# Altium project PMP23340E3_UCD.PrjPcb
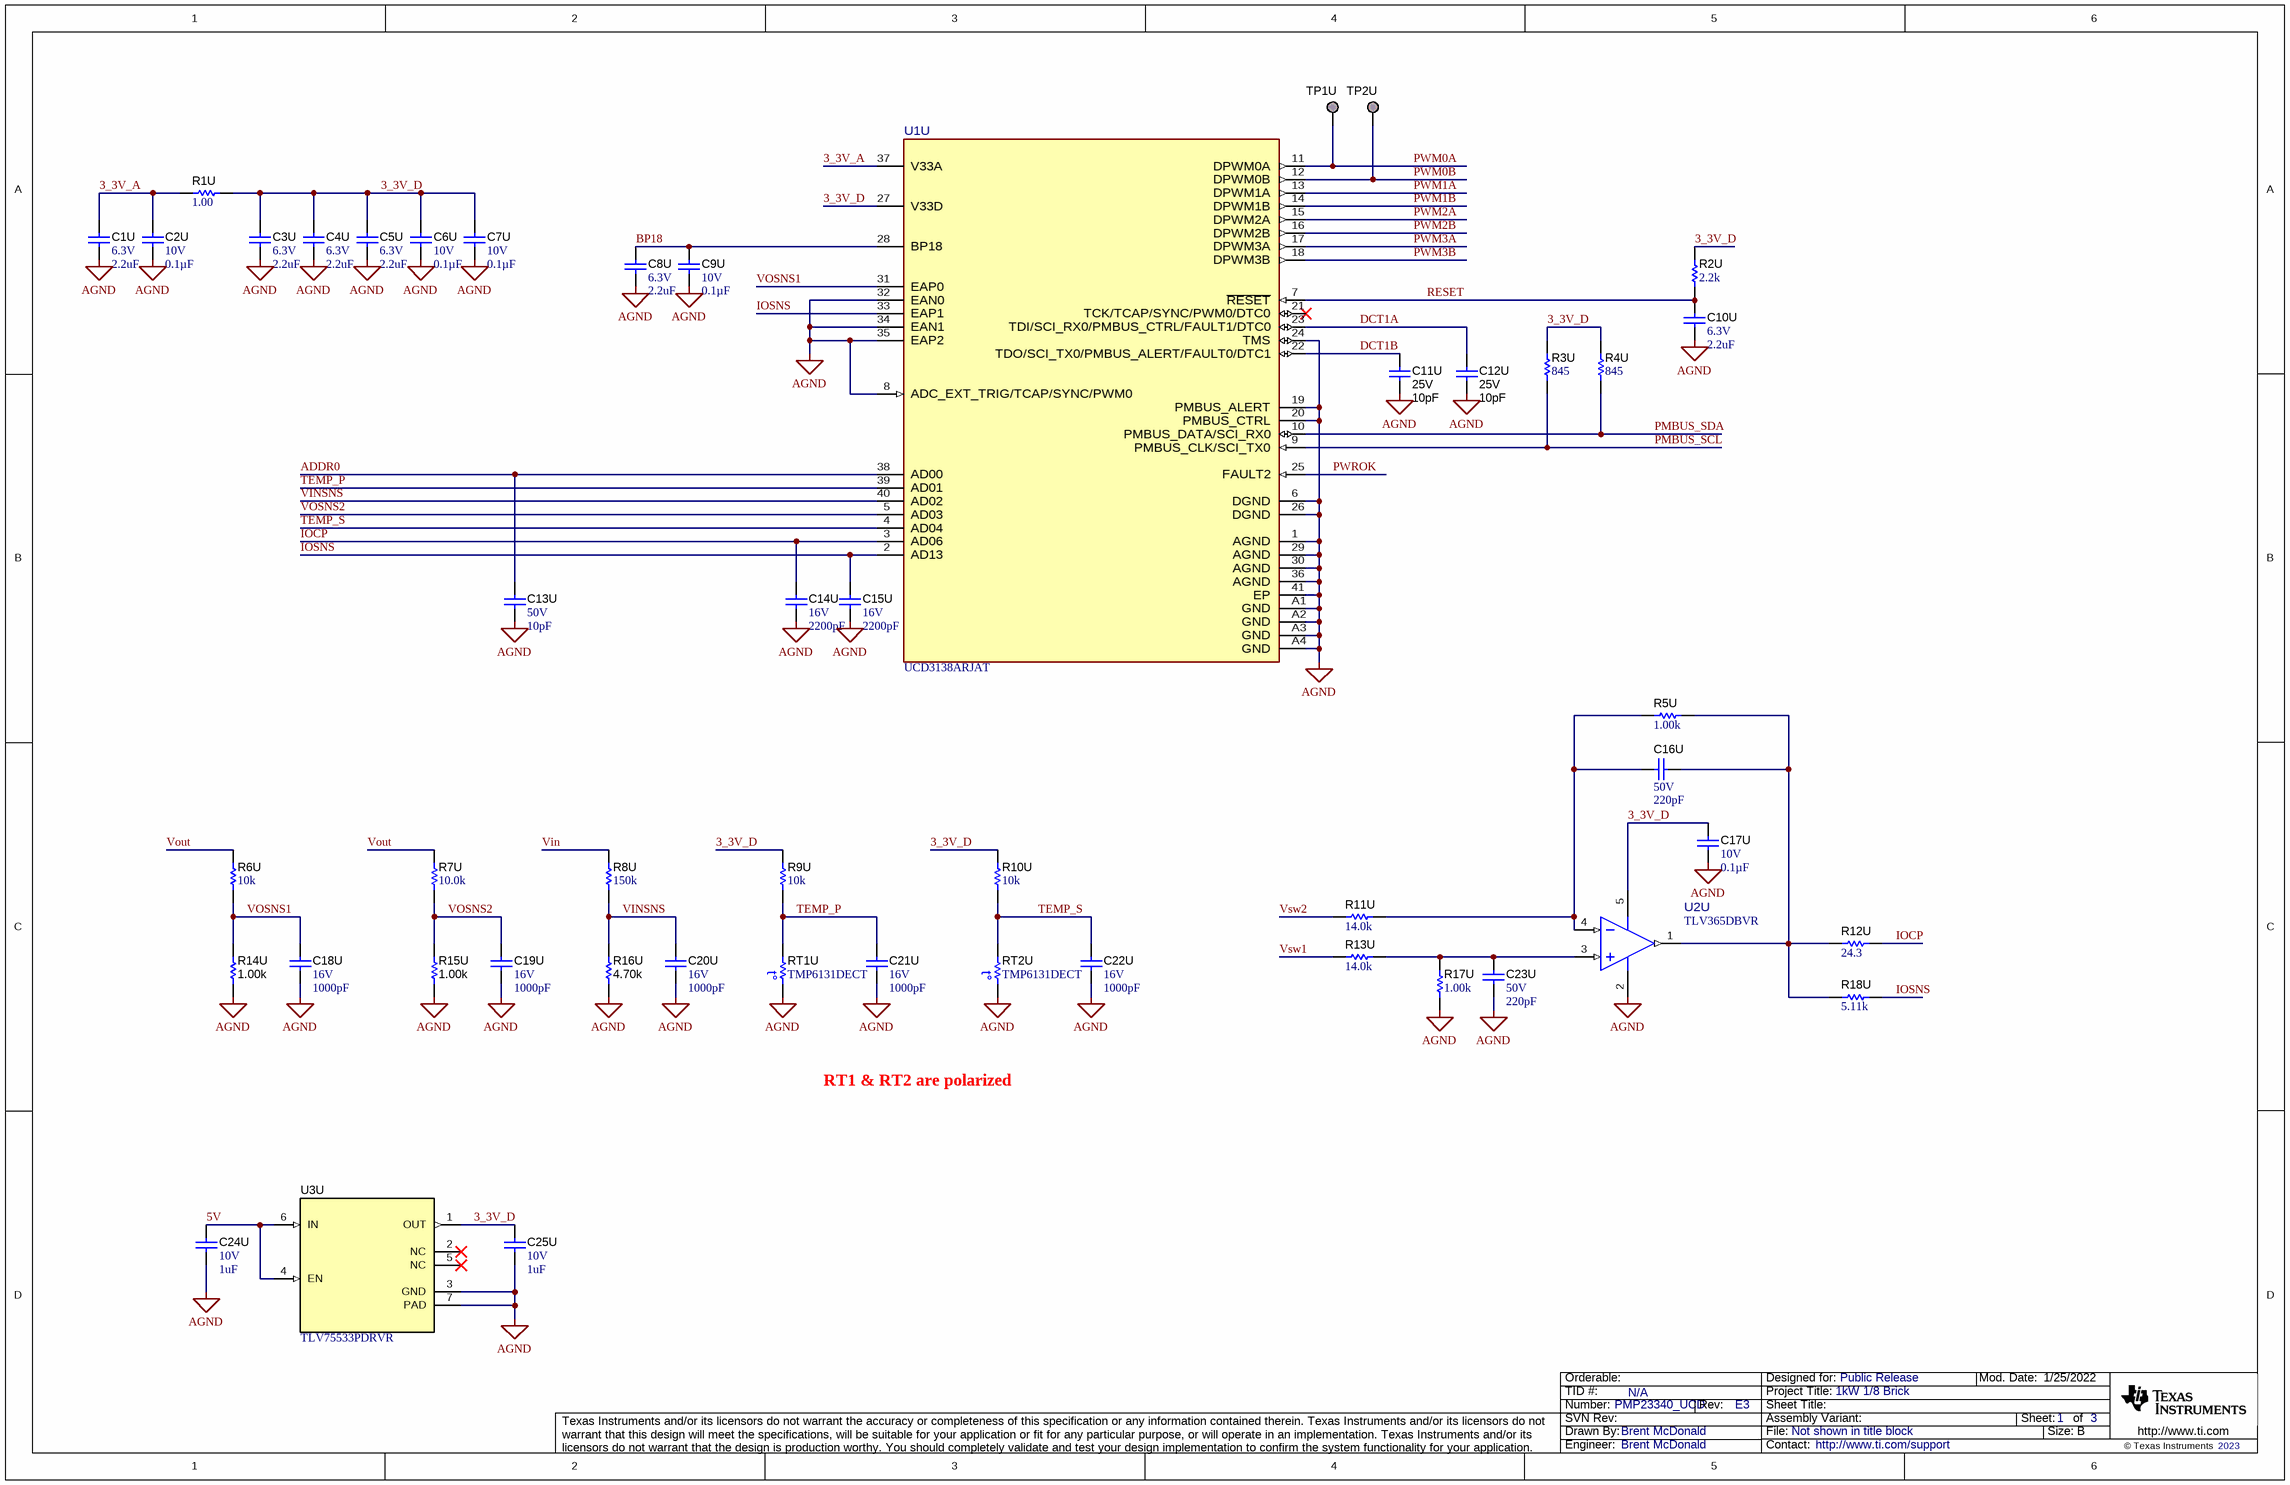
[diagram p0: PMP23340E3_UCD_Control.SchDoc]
CopyrightYear: 2023; DrawnBy: Brent McDonald; PCB_Layout: Brent McDonald; PCB_Rev: E3; PRJ_Customer: Public Release; PRJ_Engineer: Brent McDonald; PRJ_Number: PMP23340_UCD; PRJ_Title: 1kW 1/8 Brick; SCH_Rev: E3; TechSupport: http://www.ti.com/support; TID: N/A
3 sheets, 243 parts. Net scope: global (net labels, ports and power ports of the same name join across sheets).
Board file: PMP23340E3_UCD.PcbDoc
Sheets:
  PMP23340E3_UCD_Control.SchDoc
  PMP23340E3_UCD_Power_Stage.SchDoc
  PMP23340E3_UCD_Hardware.SchDoc

## Sheet PMP23340E3_UCD_Control.SchDoc
size 431 x 279 mm; Date: Not shown in title block; ApprovedBy: Not shown in title block; CheckedBy: Not shown in title block; Author: Not shown in title block; CompanyName: Not shown in title block; Engineer: Not shown in title block; Organization: Not shown in title block; Address1: Not shown in title block; Address2: Not shown in title block; Address3: Not shown in title block; Address4: Not shown in title block; DocumentNumber: 1; Revision: Use project parameter SCH_Rev; SheetNumber: 1; SheetTotal: 3; PageSetup: Record=PageOptions¦CenterHorizontal=True¦CenterVertical=True¦PrintScale=1.00¦XCorrection=1.00¦YCorrection=1.00¦PrintKind=0¦BorderSize=5000000¦LeftOffset=0¦BottomOffset=0¦Orientation=2¦PaperLength=1000¦PaperWidth=1000¦Scale=100¦PaperSource=15¦PrintQuality=600¦MediaType=1¦DitherType=10¦PaperKind=Letter¦PrintScaleMode=1

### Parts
C1U  VDC_V: 6.3V  ValueDisplayed: 2.2uF  [0201_040]  (hidden comment: GRM033R60J225ME47D)
C2U  VDC_V: 10V  ValueDisplayed: 0.1µF  [0201_033L]  (hidden comment: ATC530Z104KT10T)
C3U  VDC_V: 6.3V  ValueDisplayed: 2.2uF  [0201_040]  (hidden comment: GRM033R60J225ME47D)
C4U  VDC_V: 6.3V  ValueDisplayed: 2.2uF  [0201_040]  (hidden comment: GRM033R60J225ME47D)
C5U  VDC_V: 6.3V  ValueDisplayed: 2.2uF  [0201_040]  (hidden comment: GRM033R60J225ME47D)
C6U  VDC_V: 10V  ValueDisplayed: 0.1µF  [0201_033L]  (hidden comment: ATC530Z104KT10T)
C7U  VDC_V: 10V  ValueDisplayed: 0.1µF  [0201_033L]  (hidden comment: ATC530Z104KT10T)
C8U  VDC_V: 6.3V  ValueDisplayed: 2.2uF  [0201_040]  (hidden comment: GRM033R60J225ME47D)
C9U  VDC_V: 10V  ValueDisplayed: 0.1µF  [0201_033L]  (hidden comment: ATC530Z104KT10T)
C10U  VDC_V: 6.3V  ValueDisplayed: 2.2uF  [0201_040]  (hidden comment: GRM033R60J225ME47D)
C11U  VDC_V: 25V  ValueDisplayed: 10pF  [0201]  (hidden comment: GJM0335C1E100JB01D)
C12U  VDC_V: 25V  ValueDisplayed: 10pF  [0201]  (hidden comment: GJM0335C1E100JB01D)
C13U  VDC_V: 50V  ValueDisplayed: 10pF  [0201_033]  (hidden comment: GRM0335C1H100JA01D)
C14U  VDC_V: 16V  ValueDisplayed: 2200pF  [0201]  (hidden comment: GRM033R71C222KA88D)
C15U  VDC_V: 16V  ValueDisplayed: 2200pF  [0201]  (hidden comment: GRM033R71C222KA88D)
C16U  VDC_V: 50V  ValueDisplayed: 220pF  [0201_033]  (hidden comment: CGA1A2X7R1H221K030BA)
C17U  VDC_V: 10V  ValueDisplayed: 0.1µF  [0201_033L]  (hidden comment: ATC530Z104KT10T)
C18U  VDC_V: 16V  ValueDisplayed: 1000pF  [0201]  (hidden comment: GRM033R71C102KA01D)
C19U  VDC_V: 16V  ValueDisplayed: 1000pF  [0201]  (hidden comment: GRM033R71C102KA01D)
C20U  VDC_V: 16V  ValueDisplayed: 1000pF  [0201]  (hidden comment: GRM033R71C102KA01D)
C21U  VDC_V: 16V  ValueDisplayed: 1000pF  [0201]  (hidden comment: GRM033R71C102KA01D)
C22U  VDC_V: 16V  ValueDisplayed: 1000pF  [0201]  (hidden comment: GRM033R71C102KA01D)
C23U  VDC_V: 50V  ValueDisplayed: 220pF  [0201_033]  (hidden comment: CGA1A2X7R1H221K030BA)
C24U  VDC_V: 10V  ValueDisplayed: 1uF  [0201]  (hidden comment: GRM033R61A105ME15D)
C25U  VDC_V: 10V  ValueDisplayed: 1uF  [0201]  (hidden comment: GRM033R61A105ME15D)
R1U  ValueDisplayed: 1.00  [0201]  (hidden comment: RC0201FR-071RL)
R2U  ValueDisplayed: 2.2k  [0201]  (hidden comment: RC0201JR-7D2K2L)
R3U  ValueDisplayed: 845  [0201]  (hidden comment: RC0201FR-07845RL)
R4U  ValueDisplayed: 845  [0201]  (hidden comment: RC0201FR-07845RL)
R5U  ValueDisplayed: 1.00k  [0201]  (hidden comment: RC0201FS-7D1KL)
R6U  ValueDisplayed: 10k  [0201]  (hidden comment: RC0201JR-7D10KL)
R7U  ValueDisplayed: 10.0k  [0201]  (hidden comment: RC0201FS-7D10KL)
R8U  ValueDisplayed: 150k  [0402]  (hidden comment: CRCW0402150KFKED)
R9U  ValueDisplayed: 10k  [0201]  (hidden comment: RC0201JS-7D10KL)
R10U  ValueDisplayed: 10k  [0201]  (hidden comment: RC0201JS-7D10KL)
R11U  ValueDisplayed: 14.0k  [0402]  (hidden comment: RC0402FR-0714KL)
R12U  ValueDisplayed: 24.3  [0201]  (hidden comment: RC0201FS-7D24R3L)
R13U  ValueDisplayed: 14.0k  [0402]  (hidden comment: RC0402FR-0714KL)
R14U  ValueDisplayed: 1.00k  [0201]  (hidden comment: RC0201DR-071KL)
R15U  ValueDisplayed: 1.00k  [0201]  (hidden comment: RC0201DR-071KL)
R16U  ValueDisplayed: 4.70k  [0201]  (hidden comment: RC0201DR-074K7L)
R17U  ValueDisplayed: 1.00k  [0201]  (hidden comment: RC0201FS-7D1KL)
R18U  ValueDisplayed: 5.11k  [0201]  (hidden comment: RC0201FR-075K11L)
RT1U  TMP6131DECT  [DEC0002A]
RT2U  TMP6131DECT  [DEC0002A]
TP1U  TESTPOINT  [TP_25MIL-SMT]  (value not drawn)  (no BOM)
TP2U  TESTPOINT  [TP_25MIL-SMT]  (value not drawn)  (no BOM)
U1U  UCD3138ARJAT  [RJA0040A-MFG]
U2U  TLV365DBVR  [DBV0005A-MFG]
U3U  TLV75533PDRVR  [DRV0006A]

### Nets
AGND: C1U.1 C2U.2 C3U.1 C4U.1 C5U.1 C6U.2 C7U.2 C8U.1 C9U.2 C10U.1 C11U.2 C12U.2 C13U.2 C14U.1 C15U.1 C17U.2 C18U.1 C19U.1 C20U.1 C21U.1 C22U.1 C23U.1 C24U.2 C25U.2 R14U.1 R15U.1 R16U.1 R17U.1 RT1U.2 RT2U.2 U1U.1(AGND) U1U.6(DGND) U1U.8(ADC_EXT_TRIG/TCAP/SYNC/PWM0) U1U.19(PMBUS_ALERT) U1U.20(PMBUS_CTRL) U1U.24(TMS) U1U.26(DGND) U1U.29(AGND) U1U.30(AGND) U1U.32(EAN0) U1U.34(EAN1) U1U.35(EAP2) U1U.36(AGND) U1U.41(EP) U1U.A1(GND) U1U.A2(GND) U1U.A3(GND) U1U.A4(GND) U2U.2(V-) U3U.3(GND) U3U.7(PAD)
3_3V_A: C1U.2 C2U.1 R1U.1 U1U.37(V33A)
3_3V_D: C3U.2 C4U.2 C5U.2 C6U.1 C7U.1 C17U.1 C25U.1 R1U.2 R2U.2 R3U.1 R4U.1 R9U.2 R10U.2 U1U.27(V33D) U2U.5(V+) U3U.1(OUT)
5V: C24U.1 U3U.4(EN) U3U.6(IN)
ADDR0: C13U.1 U1U.38(AD00)
BP18: C8U.2 C9U.1 U1U.28(BP18)
DCT1A: C12U.1 U1U.23(TDI/SCI_RX0/PMBUS_CTRL/FAULT1/DTC0)
DCT1B: C11U.1 U1U.22(TDO/SCI_TX0/PMBUS_ALERT/FAULT0/DTC1)
IOCP: C14U.2 R12U.2 U1U.3(AD06)
IOSNS: C15U.2 R18U.2 U1U.2(AD13) U1U.33(EAP1)
PMBUS_SCL: R3U.2 U1U.9(PMBUS_CLK/SCI_TX0)
PMBUS_SDA: R4U.2 U1U.10(PMBUS_DATA/SCI_RX0)
PWM0A: TP1U.1 U1U.11(DPWM0A)
PWM0B: TP2U.1 U1U.12(DPWM0B)
PWM1A: U1U.13(DPWM1A)
PWM1B: U1U.14(DPWM1B)
PWM2A: U1U.15(DPWM2A)
PWM2B: U1U.16(DPWM2B)
PWM3A: U1U.17(DPWM3A)
PWM3B: U1U.18(DPWM3B)
PWROK: U1U.25(FAULT2)
RESET: C10U.2 R2U.1 U1U.7(~{RESET})
TEMP_P: C21U.2 R9U.1 RT1U.1 U1U.39(AD01)
TEMP_S: C22U.2 R10U.1 RT2U.1 U1U.4(AD04)
Vin: R8U.2
VINSNS: C20U.2 R8U.1 R16U.2 U1U.40(AD02)
VOSNS1: C18U.2 R6U.1 R14U.2 U1U.31(EAP0)
VOSNS2: C19U.2 R7U.1 R15U.2 U1U.5(AD03)
Vout: R6U.2 R7U.2
Vsw1: R13U.1
Vsw2: R11U.1
NetC16U_1: C16U.1 R5U.1 R12U.1 R18U.1 U2U.1(VOUT)
NetC16U_2: C16U.2 R5U.2 R11U.2 U2U.4(-IN)
NetC23U_2: C23U.2 R13U.2 R17U.2 U2U.3(+IN)

Not connected (* = marked no-connect by the designer): U1U 21(TCK/TCAP/SYNC/PWM0/DTC0)*; U3U 2(NC)* 5(NC)*

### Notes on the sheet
- RT1 & RT2 are polarized

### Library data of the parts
C1U C3U C4U C5U C8U C10U = CMP-0064908-2: CAP, CERM, 2.2 uF, 6.3 V,+/- 20%, X5R, 0201; Manufacturer: MuRata; TaMin_C: -55°C; Polarized: N; SizeAreaWB_mm2: 2.08; Value1: Unknown; U/M: EA; Value: 2.2uF; TaMax_C: 85°C; SizeZ_mm: 0.4; SizeX_mm: 0.6; SizeY_mm: 0.3; Cap_Case: 0201; SizeArea_mm2: 0.18; Cap_F: 2.2µF; AEC Category: Q200
C2U C6U C7U C9U C17U = CMP-0076713-1: CAP, CERM, 0.1 µF, 10 V,+/- 10%, X5R, 0201; Manufacturer: AT Ceramics; Cap_F: 100nF; SizeAreaWB_mm2: 2.08; SizeArea_mm2: 0.18; AEC Qualified: N; AEC Category: Q200; Value: 0.1uF; TaMax_C: 85°C; SizeZ_mm: 0.33; TaMin_C: -55°C; SizeY_mm: 0.3; U/M: EA; SizeX_mm: 0.6; Cap_Case: 0201
C11U C12U = CMP-0009661-3: CAP, CERM, 10 pF, 25 V, +/- 5%, C0G/NP0, 0201; Manufacturer: MuRata; TaMin_C: -55°C; Polarized: N; SizeAreaWB_mm2: 2.08; Value1: Unknown; U/M: EA; Value: 10pF; TaMax_C: 125°C; SizeZ_mm: 0.26; SizeX_mm: 0.6; SizeY_mm: 0.3; SizeArea_mm2: 0.18; AEC Category: Q200
C13U = CMP-0086057-1: CAP, CERM, 10 pF, 50 V,+/- 5%, C0G/NP0, 0201; Manufacturer: MuRata; SizeArea_mm2: 0.18; AEC Category: Q200; SizeX_mm: 0.6; SizeZ_mm: 0.33; Value: 10pF; TaMin_C: -55°C; SizeAreaWB_mm2: 2.08; U/M: EA; AEC Qualified: N; Cap_Case: 0201; SizeY_mm: 0.3; TaMax_C: 125°C
C14U C15U = CMP-0009752-1: CAP, CERM, 2200 pF, 16 V, +/- 10%, X7R, 0201; Manufacturer: MuRata; TaMin_C: -55°C; Polarized: N; SizeAreaWB_mm2: 2.08; Value1: Unknown; U/M: EA; Value: 2200pF; TaMax_C: 125°C; SizeZ_mm: 0.26; SizeX_mm: 0.6; SizeY_mm: 0.3; SizeArea_mm2: 0.18; Cap_F: 2.2nF; AEC Category: Q200
C16U C23U = CMP-0009652-3: CAP, CERM, 220 pF, 50 V, +/- 10%, X7R, AEC-Q200 Grade 1, 0201; Manufacturer: TDK; TaMin_C: -55°C; ESR_ohm: 11.6275; Polarized: N; SizeAreaWB_mm2: 2.08; Value1: 11.6275 ohm; U/M: EA; Value: 220pF; TaMax_C: 125°C; SizeZ_mm: 0.33; SizeX_mm: 0.6; SizeY_mm: 0.3; SizeArea_mm2: 0.18; AEC Qualified: Y; IRMS_A: 200.785mA; AEC Grade: 1; AEC Category: Q200
C18U C19U C20U C21U C22U = CMP-0009745-1: CAP, CERM, 1000 pF, 16 V, +/- 10%, X7R, 0201; Manufacturer: MuRata; TaMin_C: -55°C; Polarized: N; SizeAreaWB_mm2: 2.08; Value1: Unknown; U/M: EA; Value: 1000pF; TaMax_C: 125°C; SizeZ_mm: 0.26; SizeX_mm: 0.6; SizeY_mm: 0.3; SizeArea_mm2: 0.18; Cap_F: 1nF; AEC Category: Q200
C24U C25U = CMP-0064909-1: CAP, CERM, 1 uF, 10 V,+/- 20%, X5R, 0201; Manufacturer: MuRata; TaMin_C: -55°C; Polarized: N; SizeAreaWB_mm2: 2.08; Value1: Unknown; U/M: EA; Value: 1uF; TaMax_C: 85°C; SizeZ_mm: 0.26; SizeX_mm: 0.6; SizeY_mm: 0.3; SizeArea_mm2: 0.18; Cap_F: 1µF; AEC Category: Q200
R1U = CMP-0027472-1: RES, 1.00, 1%, 0.05 W, 0201; Manufacturer: Yageo America; Power_W: 50mW; TempCo: 350 ppm/C; Value_Code: 1R00; U/M: EA; Value: 1.00; EIA_Code: E96; Res_ohm: 1; SizeX_mm: 0.6; SizeY_mm: 0.3; SizeZ_mm: 0.26; Value2: 0.05W; SizeArea_mm2: 0.18; AEC Qualified: N; VDC_V: 25V; AEC Category: Q200
R2U = CMP-0027216-1: RES, 2.2 k, 5%, 0.05 W, 0201; Manufacturer: Yageo America; Power_W: 50mW; TempCo: 200 ppm/C; Value_Code: 2k20; U/M: EA; Value: 2.2k; EIA_Code: E24; SizeX_mm: 0.6; SizeY_mm: 0.3; SizeZ_mm: 0.26; Value2: 0.05W; SizeArea_mm2: 0.18; AEC Qualified: N; VDC_V: 25V; AEC Category: Q200
R3U R4U = CMP-0027896-1: RES, 845, 1%, 0.05 W, 0201; Manufacturer: Yageo America; Power_W: 50mW; TempCo: 200 ppm/C; Value_Code: 845R; U/M: EA; Value: 845; EIA_Code: E96; SizeX_mm: 0.6; SizeY_mm: 0.3; SizeZ_mm: 0.26; Value2: 0.05W; SizeArea_mm2: 0.18; AEC Qualified: N; VDC_V: 25V; AEC Category: Q200
R5U R17U = CMP-0028084-1: RES, 1.00 k, 1%, 0.05 W, 0201; Manufacturer: Yageo America; Power_W: 50mW; TempCo: 200 ppm/C; Value_Code: 1k00; U/M: EA; Value: 1.00k; EIA_Code: E96; Res_ohm: 1k; SizeX_mm: 0.6; SizeY_mm: 0.3; SizeZ_mm: 0.26; Value2: 0.05W; SizeArea_mm2: 0.18; AEC Qualified: N; VDC_V: 25V; AEC Category: Q200
R6U = CMP-0027186-1: RES, 10 k, 5%, 0.05 W, 0201; Manufacturer: Yageo America; Power_W: 50mW; TempCo: 200 ppm/C; Value_Code: 10k0; U/M: EA; Value: 10k; EIA_Code: E24; SizeX_mm: 0.6; SizeY_mm: 0.3; SizeZ_mm: 0.26; Value2: 0.05W; SizeArea_mm2: 0.18; AEC Qualified: N; VDC_V: 25V; AEC Category: Q200
R7U = CMP-0028071-1: RES, 10.0 k, 1%, 0.05 W, 0201; Manufacturer: Yageo America; Power_W: 50mW; TempCo: 200 ppm/C; Value_Code: 10k0; Value: 10.0k; EIA_Code: E96; Res_ohm: 10k; SizeX_mm: 0.6; SizeY_mm: 0.3; SizeZ_mm: 0.26; Value2: 0.05W; SizeArea_mm2: 0.18; AEC Qualified: N; VDC_V: 25V; AEC Category: Q200; U/M: EA
R8U = CMP-0026021-3: RES, 150 k, 1%, 0.063 W, AEC-Q200 Grade 0, 0402; Manufacturer: Vishay-Dale; Power_W: 63mW; TempCo: 100 ppm/C; Value: 150k; EIA_Code: E96; SizeX_mm: 1; SizeY_mm: 0.5; SizeZ_mm: 0.6; Value2: 0.063W; AEC Qualified: Y; VDC_V: 50V; AEC Grade: 0; AEC Category: Q200
R9U R10U = CMP-0027260-1: RES, 10 k, 5%, 0.05 W, 0201; Manufacturer: Yageo America; Power_W: 50mW; TempCo: 200 ppm/C; Value_Code: 10k0; U/M: EA; Value: 10k; EIA_Code: E24; SizeX_mm: 0.6; SizeY_mm: 0.3; SizeZ_mm: 0.26; Value2: 0.05W; SizeArea_mm2: 0.18; AEC Qualified: N; VDC_V: 25V; AEC Category: Q200
R11U R13U = CMP-0860046-1: RES, 14.0 k, 1%, 0.0625 W, 0402; Manufacturer: Yageo; Power_W: 62.5mW; TempCo: 100 ppm/C; Value_Code: 14k0; Value: 14.0k; EIA_Code: E96; Res_ohm: 14k; SizeX_mm: 1; SizeY_mm: 0.5; SizeZ_mm: 0.6; AEC Qualified: N; VDC_V: 50V; AEC Category: Q200; SizeAreaWB_mm2: 3
R12U = CMP-0028092-1: RES, 24.3, 1%, 0.05 W, 0201; Manufacturer: Yageo America; Power_W: 50mW; TempCo: 200 ppm/C; Value_Code: 24R3; U/M: EA; Value: 24.3; EIA_Code: E96; SizeX_mm: 0.6; SizeY_mm: 0.3; SizeZ_mm: 0.26; Value2: 0.05W; SizeArea_mm2: 0.18; AEC Qualified: N; VDC_V: 25V; AEC Category: Q200
R14U R15U = CMP-0028149-1: RES, 1.00 k, 0.5%, 0.05 W, 0201; Manufacturer: Yageo America; Power_W: 50mW; TempCo: 200 ppm/C; Value_Code: 1k00; U/M: EA; Value: 1.00k; EIA_Code: E192; Res_ohm: 1k; SizeX_mm: 0.6; SizeY_mm: 0.3; SizeZ_mm: 0.26; Value2: 0.05W; SizeArea_mm2: 0.18; AEC Qualified: N; VDC_V: 25V; AEC Category: Q200
R16U = CMP-0028221-1: RES, 4.70 k, 0.5%, 0.05 W, 0201; Manufacturer: Yageo America; Power_W: 50mW; TempCo: 200 ppm/C; Value_Code: 4k70; U/M: EA; Value: 4.70k; EIA_Code: E192; Res_ohm: 4.7k; SizeX_mm: 0.6; SizeY_mm: 0.3; SizeZ_mm: 0.26; Value2: 0.05W; SizeArea_mm2: 0.18; AEC Qualified: N; VDC_V: 25V; AEC Category: Q200
R18U = CMP-0027788-1: RES, 5.11 k, 1%, 0.05 W, 0201; Manufacturer: Yageo America; Power_W: 50mW; TempCo: 200 ppm/C; Value_Code: 5k11; U/M: EA; Value: 5.11k; EIA_Code: E96; SizeX_mm: 0.6; SizeY_mm: 0.3; SizeZ_mm: 0.26; Value2: 0.05W; SizeArea_mm2: 0.18; AEC Qualified: N; VDC_V: 25V; AEC Category: Q200
RT1U RT2U = CMP-0084565-1: Thermistor, DEC0002A (X1SON-2); Alternate Manufacturer: Texas Instruments; Alternate PartNumber: TMP6131DECR; SizeZ_mm: 0.5; CompType: IC; AEC Category: Q200; SizeArea_mm2: 0.6; AEC Qualified: N; SizeX_mm: 1; SizeAreaWB_mm2: 3.2
TP1U TP2U = CMP-0078143-3: TEST POINT.  No entry in BOM.
U1U = CMP-0030785-1: UCD3138A Highly Integrated Digital Controller for Isolated Power 40-VQFN -40 to 125; Manufacturer: Texas Instruments; SizeZ_mm: 1mm; AEC Qualified: No; Max Supply Voltage: 3.6V; Min Supply Voltage: 1.6V; Nominal Supply Current: 105mA; Number Of Outputs: 4; Standoff Height: 0mm; TJmax_C: +125°C
U2U = CMP-0032028-2: CMOS Amplifier 1 Circuit Rail-to-Rail SOT-23-5; Manufacturer: Texas Instruments; Number Of Channels: 1; Gain Bandwidth: 50MHz; SizeZ_mm: 1.45mm; AEC Qualified: No; Input Bias Current: 0.000005uA; Input Offset Voltage: 0.4mV; Max Supply Voltage: 5.5V; Min Supply Voltage: 2.2V; Nominal Supply Current: 4.6mA; Output Current Per Channel: 85mA; Response Time: 0.2us; Standoff Height: 0mm; TaMax_C: +125°C; TaMin_C: -40°C; TJmax_C: +150°C; Voltage Gain: 120dB; AEC Category: Q200; CompType: IC
U3U = CMP-0013427-7: 500mA LDO, DRV0006A (WSON-6); Manufacturer: Texas Instruments; SizeX_mm: 2; CompType: IC; SizeZ_mm: 0.8; SizeArea_mm2: 4; SizeAreaWB_mm2: 9; U/M: EA

## Sheet PMP23340E3_UCD_Power_Stage.SchDoc
size 431 x 279 mm; Date: Not shown in title block; ApprovedBy: Not shown in title block; CheckedBy: Not shown in title block; Author: Not shown in title block; CompanyName: Not shown in title block; Engineer: Not shown in title block; Organization: Not shown in title block; Address1: Not shown in title block; Address2: Not shown in title block; Address3: Not shown in title block; Address4: Not shown in title block; DocumentNumber: 2; Revision: Use project parameter SCH_Rev; SheetNumber: 2; SheetTotal: 3; PageSetup: Record=PageOptions¦CenterHorizontal=True¦CenterVertical=True¦PrintScale=1.00¦XCorrection=1.00¦YCorrection=1.00¦PrintKind=0¦BorderSize=5000000¦LeftOffset=0¦BottomOffset=0¦Orientation=2¦PaperLength=1000¦PaperWidth=1000¦Scale=100¦PaperSource=15¦PrintQuality=600¦MediaType=1¦DitherType=10¦PaperKind=Letter¦PrintScaleMode=1
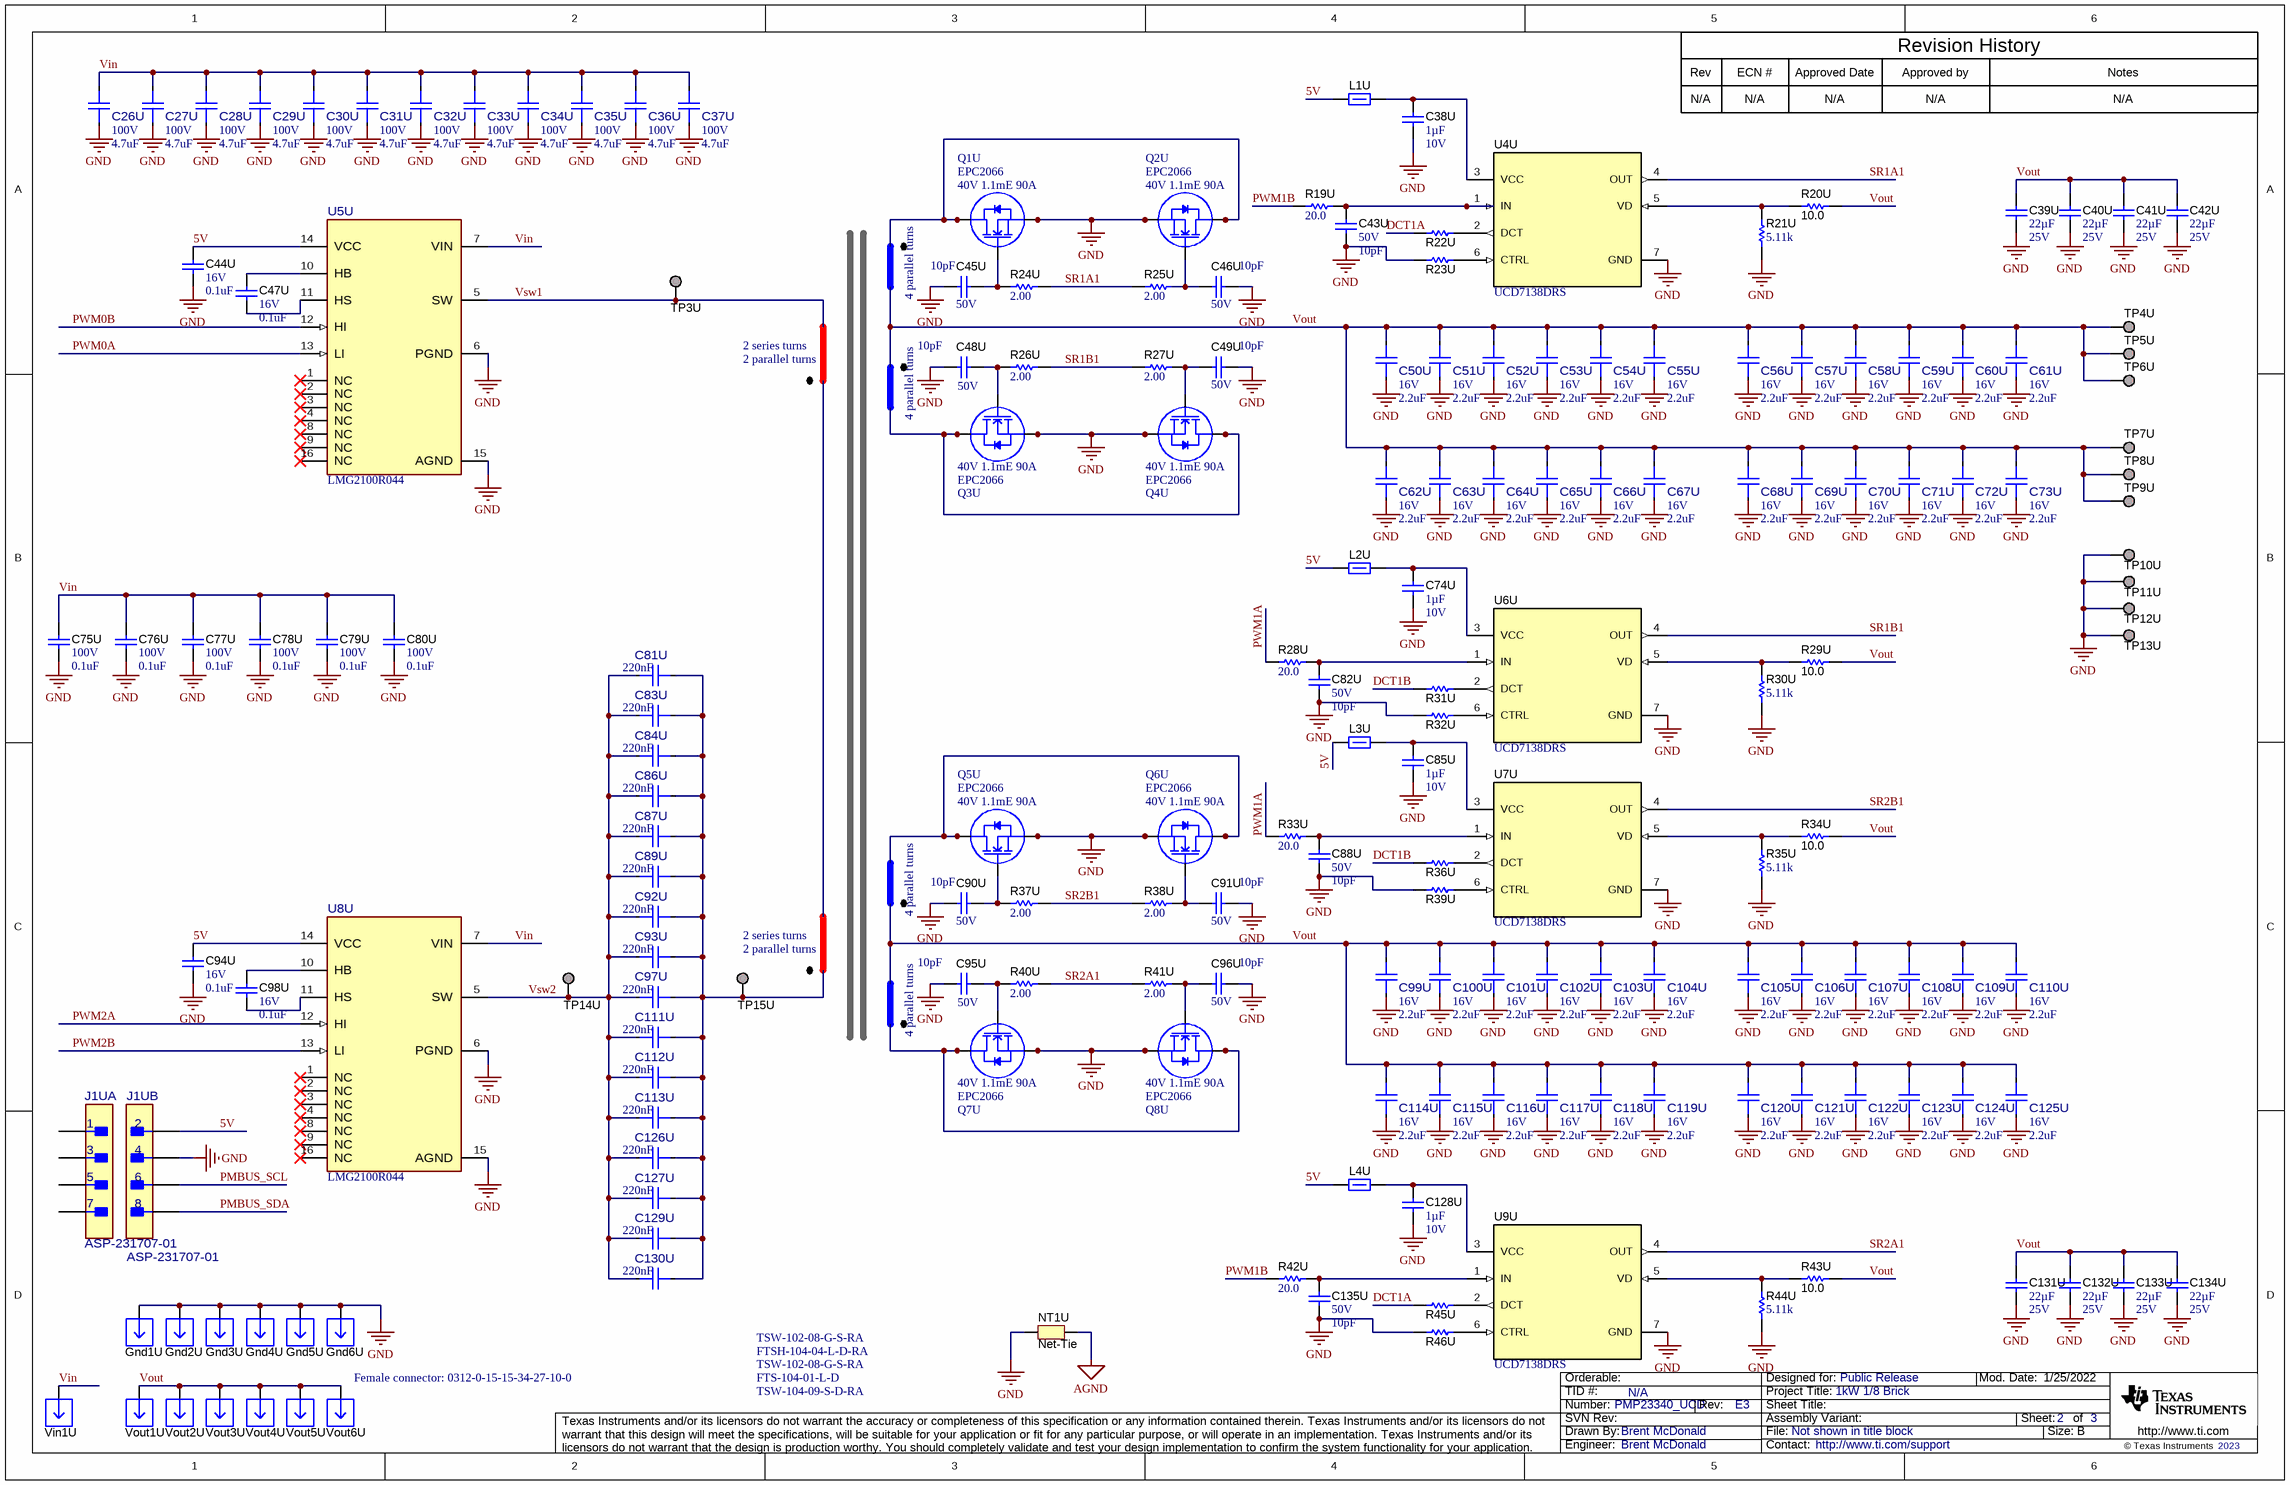
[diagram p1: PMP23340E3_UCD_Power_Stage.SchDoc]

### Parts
C26U  VDC_V: 100V  ValueDisplayed: 4.7uF  [FP-C2012X5R2A475K125AC_0805-MFG]  (hidden comment: C2012X5R2A475K125AC)
C27U  VDC_V: 100V  ValueDisplayed: 4.7uF  [FP-C2012X5R2A475K125AC_0805-MFG]  (hidden comment: C2012X5R2A475K125AC)
C28U  VDC_V: 100V  ValueDisplayed: 4.7uF  [FP-C2012X5R2A475K125AC_0805-MFG]  (hidden comment: C2012X5R2A475K125AC)
C29U  VDC_V: 100V  ValueDisplayed: 4.7uF  [FP-C2012X5R2A475K125AC_0805-MFG]  (hidden comment: C2012X5R2A475K125AC)
C30U  VDC_V: 100V  ValueDisplayed: 4.7uF  [FP-C2012X5R2A475K125AC_0805-MFG]  (hidden comment: C2012X5R2A475K125AC)
C31U  VDC_V: 100V  ValueDisplayed: 4.7uF  [FP-C2012X5R2A475K125AC_0805-MFG]  (hidden comment: C2012X5R2A475K125AC)
C32U  VDC_V: 100V  ValueDisplayed: 4.7uF  [FP-C2012X5R2A475K125AC_0805-MFG]  (hidden comment: C2012X5R2A475K125AC)
C33U  VDC_V: 100V  ValueDisplayed: 4.7uF  [FP-C2012X5R2A475K125AC_0805-MFG]  (hidden comment: C2012X5R2A475K125AC)
C34U  VDC_V: 100V  ValueDisplayed: 4.7uF  [FP-C2012X5R2A475K125AC_0805-MFG]  (hidden comment: C2012X5R2A475K125AC)
C35U  VDC_V: 100V  ValueDisplayed: 4.7uF  [FP-C2012X5R2A475K125AC_0805-MFG]  (hidden comment: C2012X5R2A475K125AC)
C36U  VDC_V: 100V  ValueDisplayed: 4.7uF  [FP-C2012X5R2A475K125AC_0805-MFG]  (hidden comment: C2012X5R2A475K125AC)
C37U  VDC_V: 100V  ValueDisplayed: 4.7uF  [FP-C2012X5R2A475K125AC_0805-MFG]  (hidden comment: C2012X5R2A475K125AC)
C38U  Cap_F: 1µF  VDC_V: 10V  [0201]  (hidden comment: GRM033R61A105ME15D)
C39U  ValueDisplayed: 22µF  VDC_V: 25V  [0805_HV]  (hidden comment: GRT21BR61E226ME13L)
C40U  ValueDisplayed: 22µF  VDC_V: 25V  [0805_HV]  (hidden comment: GRT21BR61E226ME13L)
C41U  ValueDisplayed: 22µF  VDC_V: 25V  [0805_HV]  (hidden comment: GRT21BR61E226ME13L)
C42U  ValueDisplayed: 22µF  VDC_V: 25V  [0805_HV]  (hidden comment: GRT21BR61E226ME13L)
C43U  VDC_V: 50V  ValueDisplayed: 10pF  [0201_033]  (hidden comment: GRM0335C1H100JA01D)
C44U  VDC_V: 16V  ValueDisplayed: 0.1uF  [0402_065]  (hidden comment: 160R07X104KV4T)
C45U  VDC_V: 50V  ValueDisplayed: 10pF  [0201_033]  (hidden comment: GRM0335C1H100JA01D)
C46U  VDC_V: 50V  ValueDisplayed: 10pF  [0201_033]  (hidden comment: GRM0335C1H100JA01D)
C47U  VDC_V: 16V  ValueDisplayed: 0.1uF  [0402_065]  (hidden comment: 160R07X104KV4T)
C48U  VDC_V: 50V  ValueDisplayed: 10pF  [0201_033]  (hidden comment: GRM0335C1H100JA01D)
C49U  VDC_V: 50V  ValueDisplayed: 10pF  [0201_033]  (hidden comment: GRM0335C1H100JA01D)
C50U  VDC_V: 16V  ValueDisplayed: 2.2uF  [FP-GRM155C81C225ME15D_0402-MFG]  (hidden comment: GRM155C81C225ME15D)
C51U  VDC_V: 16V  ValueDisplayed: 2.2uF  [FP-GRM155C81C225ME15D_0402-MFG]  (hidden comment: GRM155C81C225ME15D)
C52U  VDC_V: 16V  ValueDisplayed: 2.2uF  [FP-GRM155C81C225ME15D_0402-MFG]  (hidden comment: GRM155C81C225ME15D)
C53U  VDC_V: 16V  ValueDisplayed: 2.2uF  [FP-GRM155C81C225ME15D_0402-MFG]  (hidden comment: GRM155C81C225ME15D)
C54U  VDC_V: 16V  ValueDisplayed: 2.2uF  [FP-GRM155C81C225ME15D_0402-MFG]  (hidden comment: GRM155C81C225ME15D)
C55U  VDC_V: 16V  ValueDisplayed: 2.2uF  [FP-GRM155C81C225ME15D_0402-MFG]  (hidden comment: GRM155C81C225ME15D)
C56U  VDC_V: 16V  ValueDisplayed: 2.2uF  [FP-GRM155C81C225ME15D_0402-MFG]  (hidden comment: GRM155C81C225ME15D)
C57U  VDC_V: 16V  ValueDisplayed: 2.2uF  [FP-GRM155C81C225ME15D_0402-MFG]  (hidden comment: GRM155C81C225ME15D)
C58U  VDC_V: 16V  ValueDisplayed: 2.2uF  [FP-GRM155C81C225ME15D_0402-MFG]  (hidden comment: GRM155C81C225ME15D)
C59U  VDC_V: 16V  ValueDisplayed: 2.2uF  [FP-GRM155C81C225ME15D_0402-MFG]  (hidden comment: GRM155C81C225ME15D)
C60U  VDC_V: 16V  ValueDisplayed: 2.2uF  [FP-GRM155C81C225ME15D_0402-MFG]  (hidden comment: GRM155C81C225ME15D)
C61U  VDC_V: 16V  ValueDisplayed: 2.2uF  [FP-GRM155C81C225ME15D_0402-MFG]  (hidden comment: GRM155C81C225ME15D)
C62U  VDC_V: 16V  ValueDisplayed: 2.2uF  [FP-GRM155C81C225ME15D_0402-MFG]  (hidden comment: GRM155C81C225ME15D)
C63U  VDC_V: 16V  ValueDisplayed: 2.2uF  [FP-GRM155C81C225ME15D_0402-MFG]  (hidden comment: GRM155C81C225ME15D)
C64U  VDC_V: 16V  ValueDisplayed: 2.2uF  [FP-GRM155C81C225ME15D_0402-MFG]  (hidden comment: GRM155C81C225ME15D)
C65U  VDC_V: 16V  ValueDisplayed: 2.2uF  [FP-GRM155C81C225ME15D_0402-MFG]  (hidden comment: GRM155C81C225ME15D)
C66U  VDC_V: 16V  ValueDisplayed: 2.2uF  [FP-GRM155C81C225ME15D_0402-MFG]  (hidden comment: GRM155C81C225ME15D)
C67U  VDC_V: 16V  ValueDisplayed: 2.2uF  [FP-GRM155C81C225ME15D_0402-MFG]  (hidden comment: GRM155C81C225ME15D)
C68U  VDC_V: 16V  ValueDisplayed: 2.2uF  [FP-GRM155C81C225ME15D_0402-MFG]  (hidden comment: GRM155C81C225ME15D)
C69U  VDC_V: 16V  ValueDisplayed: 2.2uF  [FP-GRM155C81C225ME15D_0402-MFG]  (hidden comment: GRM155C81C225ME15D)
C70U  VDC_V: 16V  ValueDisplayed: 2.2uF  [FP-GRM155C81C225ME15D_0402-MFG]  (hidden comment: GRM155C81C225ME15D)
C71U  VDC_V: 16V  ValueDisplayed: 2.2uF  [FP-GRM155C81C225ME15D_0402-MFG]  (hidden comment: GRM155C81C225ME15D)
C72U  VDC_V: 16V  ValueDisplayed: 2.2uF  [FP-GRM155C81C225ME15D_0402-MFG]  (hidden comment: GRM155C81C225ME15D)
C73U  VDC_V: 16V  ValueDisplayed: 2.2uF  [FP-GRM155C81C225ME15D_0402-MFG]  (hidden comment: GRM155C81C225ME15D)
C74U  Cap_F: 1µF  VDC_V: 10V  [0201]  (hidden comment: GRM033R61A105ME15D)
C75U  VDC_V: 100V  ValueDisplayed: 0.1uF  [0402]  (hidden comment: GRM155R62A104KE14D)
C76U  VDC_V: 100V  ValueDisplayed: 0.1uF  [0402]  (hidden comment: GRM155R62A104KE14D)
C77U  VDC_V: 100V  ValueDisplayed: 0.1uF  [0402]  (hidden comment: GRM155R62A104KE14D)
C78U  VDC_V: 100V  ValueDisplayed: 0.1uF  [0402]  (hidden comment: GRM155R62A104KE14D)
C79U  VDC_V: 100V  ValueDisplayed: 0.1uF  [0402]  (hidden comment: GRM155R62A104KE14D)
C80U  VDC_V: 100V  ValueDisplayed: 0.1uF  [0402]  (hidden comment: GRM155R62A104KE14D)
C81U  value 220nF  [FP-C1206C224K3JAC7800_1206-MFG]  (hidden comment: C1206C224K3JAC7800)
C82U  VDC_V: 50V  ValueDisplayed: 10pF  [0201_033]  (hidden comment: GRM0335C1H100JA01D)
C83U  value 220nF  [FP-C1206C224K3JAC7800_1206-MFG]  (hidden comment: C1206C224K3JAC7800)
C84U  value 220nF  [FP-C1206C224K3JAC7800_1206-MFG]  (hidden comment: C1206C224K3JAC7800)
C85U  Cap_F: 1µF  VDC_V: 10V  [0201]  (hidden comment: GRM033R61A105ME15D)
C86U  value 220nF  [FP-C1206C224K3JAC7800_1206-MFG]  (hidden comment: C1206C224K3JAC7800)
C87U  value 220nF  [FP-C1206C224K3JAC7800_1206-MFG]  (hidden comment: C1206C224K3JAC7800)
C88U  VDC_V: 50V  ValueDisplayed: 10pF  [0201_033]  (hidden comment: GRM0335C1H100JA01D)
C89U  value 220nF  [FP-C1206C224K3JAC7800_1206-MFG]  (hidden comment: C1206C224K3JAC7800)
C90U  VDC_V: 50V  ValueDisplayed: 10pF  [0201_033]  (hidden comment: GRM0335C1H100JA01D)
C91U  VDC_V: 50V  ValueDisplayed: 10pF  [0201_033]  (hidden comment: GRM0335C1H100JA01D)
C92U  value 220nF  [FP-C1206C224K3JAC7800_1206-MFG]  (hidden comment: C1206C224K3JAC7800)
C93U  value 220nF  [FP-C1206C224K3JAC7800_1206-MFG]  (hidden comment: C1206C224K3JAC7800)
C94U  VDC_V: 16V  ValueDisplayed: 0.1uF  [0402_065]  (hidden comment: 160R07X104KV4T)
C95U  VDC_V: 50V  ValueDisplayed: 10pF  [0201_033]  (hidden comment: GRM0335C1H100JA01D)
C96U  VDC_V: 50V  ValueDisplayed: 10pF  [0201_033]  (hidden comment: GRM0335C1H100JA01D)
C97U  value 220nF  [FP-C1206C224K3JAC7800_1206-MFG]  (hidden comment: C1206C224K3JAC7800)
C98U  VDC_V: 16V  ValueDisplayed: 0.1uF  [0402_065]  (hidden comment: 160R07X104KV4T)
C99U  VDC_V: 16V  ValueDisplayed: 2.2uF  [FP-GRM155C81C225ME15D_0402-MFG]  (hidden comment: GRM155C81C225ME15D)
C100U  VDC_V: 16V  ValueDisplayed: 2.2uF  [FP-GRM155C81C225ME15D_0402-MFG]  (hidden comment: GRM155C81C225ME15D)
C101U  VDC_V: 16V  ValueDisplayed: 2.2uF  [FP-GRM155C81C225ME15D_0402-MFG]  (hidden comment: GRM155C81C225ME15D)
C102U  VDC_V: 16V  ValueDisplayed: 2.2uF  [FP-GRM155C81C225ME15D_0402-MFG]  (hidden comment: GRM155C81C225ME15D)
C103U  VDC_V: 16V  ValueDisplayed: 2.2uF  [FP-GRM155C81C225ME15D_0402-MFG]  (hidden comment: GRM155C81C225ME15D)
C104U  VDC_V: 16V  ValueDisplayed: 2.2uF  [FP-GRM155C81C225ME15D_0402-MFG]  (hidden comment: GRM155C81C225ME15D)
C105U  VDC_V: 16V  ValueDisplayed: 2.2uF  [FP-GRM155C81C225ME15D_0402-MFG]  (hidden comment: GRM155C81C225ME15D)
C106U  VDC_V: 16V  ValueDisplayed: 2.2uF  [FP-GRM155C81C225ME15D_0402-MFG]  (hidden comment: GRM155C81C225ME15D)
C107U  VDC_V: 16V  ValueDisplayed: 2.2uF  [FP-GRM155C81C225ME15D_0402-MFG]  (hidden comment: GRM155C81C225ME15D)
C108U  VDC_V: 16V  ValueDisplayed: 2.2uF  [FP-GRM155C81C225ME15D_0402-MFG]  (hidden comment: GRM155C81C225ME15D)
C109U  VDC_V: 16V  ValueDisplayed: 2.2uF  [FP-GRM155C81C225ME15D_0402-MFG]  (hidden comment: GRM155C81C225ME15D)
C110U  VDC_V: 16V  ValueDisplayed: 2.2uF  [FP-GRM155C81C225ME15D_0402-MFG]  (hidden comment: GRM155C81C225ME15D)
C111U  value 220nF  [FP-C1206C224K3JAC7800_1206-MFG]  (hidden comment: C1206C224K3JAC7800)
C112U  value 220nF  [FP-C1206C224K3JAC7800_1206-MFG]  (hidden comment: C1206C224K3JAC7800)
C113U  value 220nF  [FP-C1206C224K3JAC7800_1206-MFG]  (hidden comment: C1206C224K3JAC7800)
C114U  VDC_V: 16V  ValueDisplayed: 2.2uF  [FP-GRM155C81C225ME15D_0402-MFG]  (hidden comment: GRM155C81C225ME15D)
C115U  VDC_V: 16V  ValueDisplayed: 2.2uF  [FP-GRM155C81C225ME15D_0402-MFG]  (hidden comment: GRM155C81C225ME15D)
C116U  VDC_V: 16V  ValueDisplayed: 2.2uF  [FP-GRM155C81C225ME15D_0402-MFG]  (hidden comment: GRM155C81C225ME15D)
C117U  VDC_V: 16V  ValueDisplayed: 2.2uF  [FP-GRM155C81C225ME15D_0402-MFG]  (hidden comment: GRM155C81C225ME15D)
C118U  VDC_V: 16V  ValueDisplayed: 2.2uF  [FP-GRM155C81C225ME15D_0402-MFG]  (hidden comment: GRM155C81C225ME15D)
C119U  VDC_V: 16V  ValueDisplayed: 2.2uF  [FP-GRM155C81C225ME15D_0402-MFG]  (hidden comment: GRM155C81C225ME15D)
C120U  VDC_V: 16V  ValueDisplayed: 2.2uF  [FP-GRM155C81C225ME15D_0402-MFG]  (hidden comment: GRM155C81C225ME15D)
C121U  VDC_V: 16V  ValueDisplayed: 2.2uF  [FP-GRM155C81C225ME15D_0402-MFG]  (hidden comment: GRM155C81C225ME15D)
C122U  VDC_V: 16V  ValueDisplayed: 2.2uF  [FP-GRM155C81C225ME15D_0402-MFG]  (hidden comment: GRM155C81C225ME15D)
C123U  VDC_V: 16V  ValueDisplayed: 2.2uF  [FP-GRM155C81C225ME15D_0402-MFG]  (hidden comment: GRM155C81C225ME15D)
C124U  VDC_V: 16V  ValueDisplayed: 2.2uF  [FP-GRM155C81C225ME15D_0402-MFG]  (hidden comment: GRM155C81C225ME15D)
C125U  VDC_V: 16V  ValueDisplayed: 2.2uF  [FP-GRM155C81C225ME15D_0402-MFG]  (hidden comment: GRM155C81C225ME15D)
C126U  value 220nF  [FP-C1206C224K3JAC7800_1206-MFG]  (hidden comment: C1206C224K3JAC7800)
C127U  value 220nF  [FP-C1206C224K3JAC7800_1206-MFG]  (hidden comment: C1206C224K3JAC7800)
C128U  Cap_F: 1µF  VDC_V: 10V  [0201]  (hidden comment: GRM033R61A105ME15D)
C129U  value 220nF  [FP-C1206C224K3JAC7800_1206-MFG]  (hidden comment: C1206C224K3JAC7800)
C130U  value 220nF  [FP-C1206C224K3JAC7800_1206-MFG]  (hidden comment: C1206C224K3JAC7800)
C131U  ValueDisplayed: 22µF  VDC_V: 25V  [0805_HV]  (hidden comment: GRT21BR61E226ME13L)
C132U  ValueDisplayed: 22µF  VDC_V: 25V  [0805_HV]  (hidden comment: GRT21BR61E226ME13L)
C133U  ValueDisplayed: 22µF  VDC_V: 25V  [0805_HV]  (hidden comment: GRT21BR61E226ME13L)
C134U  ValueDisplayed: 22µF  VDC_V: 25V  [0805_HV]  (hidden comment: GRT21BR61E226ME13L)
C135U  VDC_V: 50V  ValueDisplayed: 10pF  [0201_033]  (hidden comment: GRM0335C1H100JA01D)
Gnd1U  3621-0-32-15-00-00-08-0  [Mill-Max_3621-0-32-xx-00-00-08-0]  (value not drawn)
Gnd2U  3621-0-32-15-00-00-08-0  [Mill-Max_3621-0-32-xx-00-00-08-0]  (value not drawn)
Gnd3U  3621-0-32-15-00-00-08-0  [Mill-Max_3621-0-32-xx-00-00-08-0]  (value not drawn)
Gnd4U  3621-0-32-15-00-00-08-0  [Mill-Max_3621-0-32-xx-00-00-08-0]  (value not drawn)
Gnd5U  3621-0-32-15-00-00-08-0  [Mill-Max_3621-0-32-xx-00-00-08-0]  (value not drawn)
Gnd6U  3621-0-32-15-00-00-08-0  [Mill-Max_3621-0-32-xx-00-00-08-0]  (value not drawn)
J1U  ASP-231707-01  [FP-FTSH-104-04-L-D-RA_HDR8-MFG]  (parts A,B of 2)
L1U  BLM03AX241SN1D  [0201_033]  (value not drawn)
L2U  BLM03AX241SN1D  [0201_033]  (value not drawn)
L3U  BLM03AX241SN1D  [0201_033]  (value not drawn)
L4U  BLM03AX241SN1D  [0201_033]  (value not drawn)
NT1U  Net-Tie  [NetTie_0402]  (net tie, no BOM)
Q1U  EPC2066  [D0650]
Q2U  EPC2066  [D0650]
Q3U  EPC2066  [D0650]
Q4U  EPC2066  [D0650]
Q5U  EPC2066  [D0650]
Q6U  EPC2066  [D0650]
Q7U  EPC2066  [D0650]
Q8U  EPC2066  [D0650]
R19U  ValueDisplayed: 20.0  [0201_033]  (hidden comment: CRCW020120R0FNED)
R20U  ValueDisplayed: 10.0  [0201]  (hidden comment: RC0201FS-7D10RL)
R21U  ValueDisplayed: 5.11k  [0201]  (hidden comment: RC0201DR-075K11L)
R22U  RC0201JR-070RL  [FP-RC0201JR-070RL_0201 (0603 Metric)-IPC_C]  (value not drawn)
R23U  RC0201JR-070RL  [FP-RC0201JR-070RL_0201 (0603 Metric)-IPC_C]  (value not drawn)
R24U  ValueDisplayed: 2.00  [0201]  (hidden comment: RC0201FS-7D2RL)
R25U  ValueDisplayed: 2.00  [0201]  (hidden comment: RC0201FS-7D2RL)
R26U  ValueDisplayed: 2.00  [0201]  (hidden comment: RC0201FS-7D2RL)
R27U  ValueDisplayed: 2.00  [0201]  (hidden comment: RC0201FS-7D2RL)
R28U  ValueDisplayed: 20.0  [0201_033]  (hidden comment: CRCW020120R0FNED)
R29U  ValueDisplayed: 10.0  [0201]  (hidden comment: RC0201FS-7D10RL)
R30U  ValueDisplayed: 5.11k  [0201]  (hidden comment: RC0201DR-075K11L)
R31U  RC0201JR-070RL  [FP-RC0201JR-070RL_0201 (0603 Metric)-IPC_C]  (value not drawn)
R32U  RC0201JR-070RL  [FP-RC0201JR-070RL_0201 (0603 Metric)-IPC_C]  (value not drawn)
R33U  ValueDisplayed: 20.0  [0201_033]  (hidden comment: CRCW020120R0FNED)
R34U  ValueDisplayed: 10.0  [0201]  (hidden comment: RC0201FS-7D10RL)
R35U  ValueDisplayed: 5.11k  [0201]  (hidden comment: RC0201DR-075K11L)
R36U  RC0201JR-070RL  [FP-RC0201JR-070RL_0201 (0603 Metric)-IPC_C]  (value not drawn)
R37U  ValueDisplayed: 2.00  [0201]  (hidden comment: RC0201FS-7D2RL)
R38U  ValueDisplayed: 2.00  [0201]  (hidden comment: RC0201FS-7D2RL)
R39U  RC0201JR-070RL  [FP-RC0201JR-070RL_0201 (0603 Metric)-IPC_C]  (value not drawn)
R40U  ValueDisplayed: 2.00  [0201]  (hidden comment: RC0201FS-7D2RL)
R41U  ValueDisplayed: 2.00  [0201]  (hidden comment: RC0201FS-7D2RL)
R42U  ValueDisplayed: 20.0  [0201_033]  (hidden comment: CRCW020120R0FNED)
R43U  ValueDisplayed: 10.0  [0201]  (hidden comment: RC0201FS-7D10RL)
R44U  ValueDisplayed: 5.11k  [0201]  (hidden comment: RC0201DR-075K11L)
R45U  RC0201JR-070RL  [FP-RC0201JR-070RL_0201 (0603 Metric)-IPC_C]  (value not drawn)
R46U  RC0201JR-070RL  [FP-RC0201JR-070RL_0201 (0603 Metric)-IPC_C]  (value not drawn)
TP3U  TESTPOINT  [TP_25MIL-SMT]  (value not drawn)  (no BOM)
TP4U  TESTPOINT  [TP_25MIL-SMT]  (value not drawn)  (no BOM)
TP5U  TESTPOINT  [TP_25MIL-SMT]  (value not drawn)  (no BOM)
TP6U  TESTPOINT  [TP_25MIL-SMT]  (value not drawn)  (no BOM)
TP7U  TESTPOINT  [TP_25MIL-SMT]  (value not drawn)  (no BOM)
TP8U  TESTPOINT  [TP_25MIL-SMT]  (value not drawn)  (no BOM)
TP9U  TESTPOINT  [TP_25MIL-SMT]  (value not drawn)  (no BOM)
TP10U  TESTPOINT  [TP_25MIL-SMT]  (value not drawn)  (no BOM)
TP11U  TESTPOINT  [TP_25MIL-SMT]  (value not drawn)  (no BOM)
TP12U  TESTPOINT  [TP_25MIL-SMT]  (value not drawn)  (no BOM)
TP13U  TESTPOINT  [TP_25MIL-SMT]  (value not drawn)  (no BOM)
TP14U  TESTPOINT  [TP_25MIL-SMT]  (value not drawn)  (no BOM)
TP15U  TESTPOINT  [TP_25MIL-SMT]  (value not drawn)  (no BOM)
U4U  UCD7138DRS  [DRS0006A]
U5U  LMG2100R044  [RAR0016A-MFG]
U6U  UCD7138DRS  [DRS0006A]
U7U  UCD7138DRS  [DRS0006A]
U8U  LMG2100R044  [RAR0016A-MFG]
U9U  UCD7138DRS  [DRS0006A]
Vin1U  3621-0-32-15-00-00-08-0  [Mill-Max_3621-0-32-xx-00-00-08-0]  (value not drawn)
Vout1U  3621-0-32-15-00-00-08-0  [Mill-Max_3621-0-32-xx-00-00-08-0]  (value not drawn)
Vout2U  3621-0-32-15-00-00-08-0  [Mill-Max_3621-0-32-xx-00-00-08-0]  (value not drawn)
Vout3U  3621-0-32-15-00-00-08-0  [Mill-Max_3621-0-32-xx-00-00-08-0]  (value not drawn)
Vout4U  3621-0-32-15-00-00-08-0  [Mill-Max_3621-0-32-xx-00-00-08-0]  (value not drawn)
Vout5U  3621-0-32-15-00-00-08-0  [Mill-Max_3621-0-32-xx-00-00-08-0]  (value not drawn)
Vout6U  3621-0-32-15-00-00-08-0  [Mill-Max_3621-0-32-xx-00-00-08-0]  (value not drawn)

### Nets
AGND: NT1U.2
GND: C26U.1 C27U.1 C28U.1 C29U.1 C30U.1 C31U.1 C32U.1 C33U.1 C34U.1 C35U.1 C36U.1 C37U.1 C38U.2 C39U.2 C40U.2 C41U.2 C42U.2 C43U.1 C44U.1 C45U.1 C46U.2 C48U.1 C49U.2 C50U.1 C51U.1 C52U.1 C53U.1 C54U.1 C55U.1 C56U.1 C57U.1 C58U.1 C59U.1 C60U.1 C61U.1 C62U.1 C63U.1 C64U.1 C65U.1 C66U.1 C67U.1 C68U.1 C69U.1 C70U.1 C71U.1 C72U.1 C73U.1 C74U.2 C75U.2 C76U.2 C77U.2 C78U.2 C79U.2 C80U.2 C82U.1 C85U.2 C88U.1 C90U.1 C91U.2 C94U.1 C95U.1 C96U.2 C99U.1 C100U.1 C101U.1 C102U.1 C103U.1 C104U.1 C105U.1 C106U.1 C107U.1 C108U.1 C109U.1 C110U.1 C114U.1 C115U.1 C116U.1 C117U.1 C118U.1 C119U.1 C120U.1 C121U.1 C122U.1 C123U.1 C124U.1 C125U.1 C128U.2 C131U.2 C132U.2 C133U.2 C134U.2 C135U.1 Gnd1U.1 Gnd2U.1 Gnd3U.1 Gnd4U.1 Gnd5U.1 Gnd6U.1 J1U.4 NT1U.1 Q1U.2(S1) Q1U.5(S2) Q1U.6(S3) Q1U.9(S4) Q1U.10(S5) Q1U.13(S6) Q1U.14(S7) Q1U.17(S8) Q1U.18(S9) Q1U.21(S10) Q1U.22(S11) Q1U.25(S12) Q1U.26(S13) Q1U.29(S14) Q1U.30(Sub) Q2U.2(S1) Q2U.5(S2) Q2U.6(S3) Q2U.9(S4) Q2U.10(S5) Q2U.13(S6) Q2U.14(S7) Q2U.17(S8) Q2U.18(S9) Q2U.21(S10) Q2U.22(S11) Q2U.25(S12) Q2U.26(S13) Q2U.29(S14) Q2U.30(Sub) Q3U.2(S1) Q3U.5(S2) Q3U.6(S3) Q3U.9(S4) Q3U.10(S5) Q3U.13(S6) Q3U.14(S7) Q3U.17(S8) Q3U.18(S9) Q3U.21(S10) Q3U.22(S11) Q3U.25(S12) Q3U.26(S13) Q3U.29(S14) Q3U.30(Sub) Q4U.2(S1) Q4U.5(S2) Q4U.6(S3) Q4U.9(S4) Q4U.10(S5) Q4U.13(S6) Q4U.14(S7) Q4U.17(S8) Q4U.18(S9) Q4U.21(S10) Q4U.22(S11) Q4U.25(S12) Q4U.26(S13) Q4U.29(S14) Q4U.30(Sub) Q5U.2(S1) Q5U.5(S2) Q5U.6(S3) Q5U.9(S4) Q5U.10(S5) Q5U.13(S6) Q5U.14(S7) Q5U.17(S8) Q5U.18(S9) Q5U.21(S10) Q5U.22(S11) Q5U.25(S12) Q5U.26(S13) Q5U.29(S14) Q5U.30(Sub) Q6U.2(S1) Q6U.5(S2) Q6U.6(S3) Q6U.9(S4) Q6U.10(S5) Q6U.13(S6) Q6U.14(S7) Q6U.17(S8) Q6U.18(S9) Q6U.21(S10) Q6U.22(S11) Q6U.25(S12) Q6U.26(S13) Q6U.29(S14) Q6U.30(Sub) Q7U.2(S1) Q7U.5(S2) Q7U.6(S3) Q7U.9(S4) Q7U.10(S5) Q7U.13(S6) Q7U.14(S7) Q7U.17(S8) Q7U.18(S9) Q7U.21(S10) Q7U.22(S11) Q7U.25(S12) Q7U.26(S13) Q7U.29(S14) Q7U.30(Sub) Q8U.2(S1) Q8U.5(S2) Q8U.6(S3) Q8U.9(S4) Q8U.10(S5) Q8U.13(S6) Q8U.14(S7) Q8U.17(S8) Q8U.18(S9) Q8U.21(S10) Q8U.22(S11) Q8U.25(S12) Q8U.26(S13) Q8U.29(S14) Q8U.30(Sub) R21U.1 R23U.1 R30U.1 R32U.1 R35U.1 R39U.1 R44U.1 R46U.1 TP10U.1 TP11U.1 TP12U.1 TP13U.1 U4U.7(GND) U5U.6(PGND) U5U.15(AGND) U6U.7(GND) U7U.7(GND) U8U.6(PGND) U8U.15(AGND) U9U.7(GND)
5V: C44U.2 C94U.2 J1U.2 L1U.1 L2U.1 L3U.1 L4U.1 U5U.14(VCC) U8U.14(VCC)
DCT1A: R22U.1 R45U.1
DCT1B: R31U.1 R36U.1
PMBUS_SCL: J1U.6
PMBUS_SDA: J1U.8
PWM0A: U5U.13(LI)
PWM0B: U5U.12(HI)
PWM1A: R28U.1 R33U.1
PWM1B: R19U.1 R42U.1
PWM2A: U8U.12(HI)
PWM2B: U8U.13(LI)
SR1A1: R24U.2 R25U.1 U4U.4(OUT)
SR1B1: R26U.2 R27U.1 U6U.4(OUT)
SR2A1: R40U.2 R41U.1 U9U.4(OUT)
SR2B1: R37U.2 R38U.1 U7U.4(OUT)
Vin: C26U.2 C27U.2 C28U.2 C29U.2 C30U.2 C31U.2 C32U.2 C33U.2 C34U.2 C35U.2 C36U.2 C37U.2 C75U.1 C76U.1 C77U.1 C78U.1 C79U.1 C80U.1 U5U.7(VIN) U8U.7(VIN) Vin1U.1
Vout: C39U.1 C40U.1 C41U.1 C42U.1 C50U.2 C51U.2 C52U.2 C53U.2 C54U.2 C55U.2 C56U.2 C57U.2 C58U.2 C59U.2 C60U.2 C61U.2 C62U.2 C63U.2 C64U.2 C65U.2 C66U.2 C67U.2 C68U.2 C69U.2 C70U.2 C71U.2 C72U.2 C73U.2 C99U.2 C100U.2 C101U.2 C102U.2 C103U.2 C104U.2 C105U.2 C106U.2 C107U.2 C108U.2 C109U.2 C110U.2 C114U.2 C115U.2 C116U.2 C117U.2 C118U.2 C119U.2 C120U.2 C121U.2 C122U.2 C123U.2 C124U.2 C125U.2 C131U.1 C132U.1 C133U.1 C134U.1 Q1U.3(D1) Q1U.4(D2) Q1U.7(D3) Q1U.8(D4) Q1U.11(D5) Q1U.12(D6) Q1U.15(D7) Q1U.16(D8) Q1U.19(D9) Q1U.20(D10) Q1U.23(D11) Q1U.24(D12) Q1U.27(D13) Q1U.28(D14) Q2U.3(D1) Q2U.4(D2) Q2U.7(D3) Q2U.8(D4) Q2U.11(D5) Q2U.12(D6) Q2U.15(D7) Q2U.16(D8) Q2U.19(D9) Q2U.20(D10) Q2U.23(D11) Q2U.24(D12) Q2U.27(D13) Q2U.28(D14) Q3U.3(D1) Q3U.4(D2) Q3U.7(D3) Q3U.8(D4) Q3U.11(D5) Q3U.12(D6) Q3U.15(D7) Q3U.16(D8) Q3U.19(D9) Q3U.20(D10) Q3U.23(D11) Q3U.24(D12) Q3U.27(D13) Q3U.28(D14) Q4U.3(D1) Q4U.4(D2) Q4U.7(D3) Q4U.8(D4) Q4U.11(D5) Q4U.12(D6) Q4U.15(D7) Q4U.16(D8) Q4U.19(D9) Q4U.20(D10) Q4U.23(D11) Q4U.24(D12) Q4U.27(D13) Q4U.28(D14) Q5U.3(D1) Q5U.4(D2) Q5U.7(D3) Q5U.8(D4) Q5U.11(D5) Q5U.12(D6) Q5U.15(D7) Q5U.16(D8) Q5U.19(D9) Q5U.20(D10) Q5U.23(D11) Q5U.24(D12) Q5U.27(D13) Q5U.28(D14) Q6U.3(D1) Q6U.4(D2) Q6U.7(D3) Q6U.8(D4) Q6U.11(D5) Q6U.12(D6) Q6U.15(D7) Q6U.16(D8) Q6U.19(D9) Q6U.20(D10) Q6U.23(D11) Q6U.24(D12) Q6U.27(D13) Q6U.28(D14) Q7U.3(D1) Q7U.4(D2) Q7U.7(D3) Q7U.8(D4) Q7U.11(D5) Q7U.12(D6) Q7U.15(D7) Q7U.16(D8) Q7U.19(D9) Q7U.20(D10) Q7U.23(D11) Q7U.24(D12) Q7U.27(D13) Q7U.28(D14) Q8U.3(D1) Q8U.4(D2) Q8U.7(D3) Q8U.8(D4) Q8U.11(D5) Q8U.12(D6) Q8U.15(D7) Q8U.16(D8) Q8U.19(D9) Q8U.20(D10) Q8U.23(D11) Q8U.24(D12) Q8U.27(D13) Q8U.28(D14) R20U.2 R29U.2 R34U.2 R43U.2 TP4U.1 TP5U.1 TP6U.1 TP7U.1 TP8U.1 TP9U.1 Vout1U.1 Vout2U.1 Vout3U.1 Vout4U.1 Vout5U.1 Vout6U.1
Vsw1: C81U.2 C83U.2 C84U.2 C86U.2 C87U.2 C89U.2 C92U.2 C93U.2 C97U.2 C111U.2 C112U.2 C113U.2 C126U.2 C127U.2 C129U.2 C130U.2 TP3U.1 TP15U.1 U5U.5(SW)
Vsw2: C81U.1 C83U.1 C84U.1 C86U.1 C87U.1 C89U.1 C92U.1 C93U.1 C97U.1 C111U.1 C112U.1 C113U.1 C126U.1 C127U.1 C129U.1 C130U.1 TP14U.1 U8U.5(SW)
NetC38U_1: C38U.1 L1U.2 U4U.3(VCC)
NetC43U_2: C43U.2 R19U.2 U4U.1(IN)
NetC45U_2: C45U.2 Q1U.1(G) R24U.1
NetC46U_1: C46U.1 Q2U.1(G) R25U.2
NetC47U_1: C47U.1 U5U.10(HB)
NetC47U_2: C47U.2 U5U.11(HS)
NetC48U_2: C48U.2 Q3U.1(G) R26U.1
NetC49U_1: C49U.1 Q4U.1(G) R27U.2
NetC74U_1: C74U.1 L2U.2 U6U.3(VCC)
NetC82U_2: C82U.2 R28U.2 U6U.1(IN)
NetC85U_1: C85U.1 L3U.2 U7U.3(VCC)
NetC88U_2: C88U.2 R33U.2 U7U.1(IN)
NetC90U_2: C90U.2 Q5U.1(G) R37U.1
NetC91U_1: C91U.1 Q6U.1(G) R38U.2
NetC95U_2: C95U.2 Q7U.1(G) R40U.1
NetC96U_1: C96U.1 Q8U.1(G) R41U.2
NetC98U_1: C98U.1 U8U.10(HB)
NetC98U_2: C98U.2 U8U.11(HS)
NetC128U_1: C128U.1 L4U.2 U9U.3(VCC)
NetC135U_2: C135U.2 R42U.2 U9U.1(IN)
NetR20U_1: R20U.1 R21U.2 U4U.5(VD)
NetR22U_2: R22U.2 U4U.2(DCT)
NetR23U_2: R23U.2 U4U.6(CTRL)
NetR29U_1: R29U.1 R30U.2 U6U.5(VD)
NetR31U_2: R31U.2 U6U.2(DCT)
NetR32U_2: R32U.2 U6U.6(CTRL)
NetR34U_1: R34U.1 R35U.2 U7U.5(VD)
NetR36U_2: R36U.2 U7U.2(DCT)
NetR39U_2: R39U.2 U7U.6(CTRL)
NetR43U_1: R43U.1 R44U.2 U9U.5(VD)
NetR45U_2: R45U.2 U9U.2(DCT)
NetR46U_2: R46U.2 U9U.6(CTRL)

Not connected (* = marked no-connect by the designer): J1U 1 3 5 7; U5U 1(NC)* 2(NC)* 3(NC)* 4(NC)* 8(NC)* 9(NC)* 16(NC)*; U8U 1(NC)* 2(NC)* 3(NC)* 4(NC)* 8(NC)* 9(NC)* 16(NC)*

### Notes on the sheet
- Rev
- N/A
- ECN #
- Approved Date
- Approved by
- Revision History
- Notes
- 4 parallel turns
- 2 series turns
- 2 parallel turns
- (near TP15U) 2 series turns
- (near TP15U) 2 parallel turns
- TSW-102-08-G-S-RA
- FTSH-104-04-L-D-RA
- (near Vout6U) Female connector: 0312-0-15-15-34-27-10-0
- FTS-104-01-L-D
- TSW-104-09-S-D-RA

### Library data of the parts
C26U C27U C28U C29U C30U C31U C32U C33U C34U C35U C36U C37U = CMP-0098058-1: 4.7 µF ±10% 100V Ceramic Capacitor X5R 0805 (2012 Metric); Manufacturer: TDK; TempCo: 15%; Value: 4.7µF; SizeZ_mm: 1.5mm; AEC Qualified: No
C38U C74U C85U C128U = CMP-0064909-1: CAP, CERM, 1 uF, 10 V,+/- 20%, X5R, 0201; Manufacturer: MuRata; TaMin_C: -55°C; Polarized: N; SizeAreaWB_mm2: 2.08; Value1: Unknown; U/M: EA; Value: 1uF; TaMax_C: 85°C; SizeZ_mm: 0.26; SizeX_mm: 0.6; SizeY_mm: 0.3; SizeArea_mm2: 0.18; AEC Category: Q200
C39U C40U C41U C42U C131U C132U C133U C134U = CMP-0084680-1: CAP, CERM, 22 µF, 25 V,+/- 20%, X5R, AEC-Q200 Grade 3, 0805; Manufacturer: MuRata; SizeX_mm: 2; SizeAreaWB_mm2: 6.75; Cap_Case: 0805; AEC Grade: 3; SizeY_mm: 1.25; SizeArea_mm2: 2.5; SizeZ_mm: 1.45; U/M: EA; Polarized: N; AEC Category: Q200; Value: 22uF; TaMin_C: -55°C; AEC Qualified: Y; TaMax_C: 85°C
C43U C45U C46U C48U C49U C82U C88U C90U C91U C95U C96U C135U = CMP-0086057-1: as C13U on sheet PMP23340E3_UCD_Control
C44U C47U C94U C98U = CMP-0006204-2: CAP, CERM, 0.1 uF, 16 V, +/- 10%, X5R, 0402; Manufacturer: Johanson Technology; TaMin_C: -55°C; Polarized: N; SizeAreaWB_mm2: 3; Value1: Unknown; U/M: EA; Value: 0.1uF; TaMax_C: 85°C; SizeZ_mm: 0.65; SizeX_mm: 1; SizeY_mm: 0.5; Cap_Case: 0402; Cap_F: 100nF; AEC Category: Q200
C50U C51U C52U C53U C54U C55U C56U C57U C58U C59U C60U C61U C62U C63U C64U C65U C66U C67U C68U C69U C70U C71U C72U C73U C99U C100U C101U C102U C103U C104U C105U C106U C107U C108U C109U C110U C114U C115U C116U C117U C118U C119U C120U C121U C122U C123U C124U C125U = CMP-0001414-1: Chip Multilayer Ceramic Capacitors for General Purpose, 0402, 2.2uF, X6S, 22%, 20%, 16V; Manufacturer: Murata; Value: 2.2µF; SizeZ_mm: 0.55mm; AEC Qualified: No
C75U C76U C77U C78U C79U C80U = CMP-0006618-2: CAP, CERM, 0.1 uF, 100 V, +/- 10%, X5R, 0402; Manufacturer: MuRata; TaMin_C: -55°C; Polarized: N; SizeAreaWB_mm2: 3; Value1: Unknown; U/M: EA; Value: 0.1uF; TaMax_C: 85°C; SizeZ_mm: 0.6; SizeX_mm: 1; SizeY_mm: 0.5; Cap_F: 100nF; AEC Category: Q200
C81U C83U C84U C86U C87U C89U C92U C93U C97U C111U C112U C113U C126U C127U C129U C130U = CMP-0001410-1: 0.22 µF ±10% 25V Ceramic Capacitor U2J 1206 (3216 Metric); Manufacturer: KEMET; TempCo: -750+/-120ppm/°C; SizeZ_mm: 1.8mm; AEC Qualified: No; ValueDisplayed: 0.22uF
Gnd1U Gnd2U Gnd3U Gnd4U Gnd5U Gnd6U Vin1U Vout1U Vout2U Vout3U Vout4U Vout5U Vout6U = CMP-0082316-1: PCB Pin, 0.04" DIA, Edge-Mount; Manufacturer: Mill-Max; CompType: PCB Pin; ContactFinish: Gold; Gender: Male; Row_Count: 1
J1U = CMP-0003661-1: Like part: FTSH-104-04-L-D-RA; Manufacturer: Samtec; ContactFinish: Gold,Nickel; Current_A: 3.4A; Row_Count: 2; AEC Qualified: No; Conn Gender: Male; Conn Orientation: Right Angle; DUT-Pitch_mm: 1.27mm; SizeZ_mm: 3.56mm; TaMax_C: +125°C; TaMin_C: -55°C
L1U L2U L3U L4U = CMP-0084501-1: Inductor, Ferrite Bead, Ferrite, 0.35 A, 0.38 ohm, SMD; Manufacturer: MuRata; SizeX_mm: 0.6; SizeY_mm: 0.3; Imax_A: 350mA; AEC Category: Q200; SizeArea_mm2: 0.18; SizeZ_mm: 0.33; SizeAreaWB_mm2: 2.08; Value2: 0.35A; AEC Qualified: N; DCR_ohm: 0.38
NT1U = CMP-0078142-6: Single point connection between nets.
Q1U Q2U Q3U Q4U Q5U Q6U Q7U Q8U = EPC2066: 40V 1.1mE 90A; MFG: EPC; Name: Aspen
R19U R28U R33U R42U = CMP-0078192-2: RES, 20.0, 1%, 0.05 W, 0201; Manufacturer: Vishay-Dale; Value_Code: 20R0; SizeArea_mm2: 0.18; AEC Qualified: N; AEC Category: Q200; Res_ohm: 20; Value: 20.0; SizeZ_mm: 0.33; EIA_Code: E96; TempCo: 200 ppm/C; Power_W: 50mW; VDC_V: 30V; SizeY_mm: 0.3; Value2: 0.05W; SizeX_mm: 0.6
R20U R29U R34U R43U = CMP-0028072-1: RES, 10.0, 1%, 0.05 W, 0201; Manufacturer: Yageo America; Power_W: 50mW; TempCo: 350 ppm/C; Value_Code: 10R0; U/M: EA; Value: 10.0; EIA_Code: E96; Res_ohm: 10; SizeX_mm: 0.6; SizeY_mm: 0.3; SizeZ_mm: 0.26; Value2: 0.05W; SizeArea_mm2: 0.18; AEC Qualified: N; VDC_V: 25V; AEC Category: Q200
R21U R30U R35U R44U = CMP-0028226-1: RES, 5.11 k, 0.5%, 0.05 W, 0201; Manufacturer: Yageo America; Power_W: 50mW; TempCo: 200 ppm/C; Value_Code: 5k11; U/M: EA; Value: 5.11k; EIA_Code: E192; SizeX_mm: 0.6; SizeY_mm: 0.3; SizeZ_mm: 0.26; Value2: 0.05W; SizeArea_mm2: 0.18; AEC Qualified: N; VDC_V: 25V; AEC Category: Q200
R22U R23U R31U R32U R36U R39U R45U R46U = CMP-0086442-2: RES SMD 0 OHM JUMPER 1/20W 0201; Manufacturer: Yageo; Power_W: 50mW; VDC_V: 25V; AEC Qualified: No; Res_ohm: 0; Tolerance_%: 5%; TempCo: 200ppm/°C; SizeZ_mm: 0.26mm
R24U R25U R26U R27U R37U R38U R40U R41U = CMP-0028098-1: RES, 2.00, 1%, 0.05 W, 0201; Manufacturer: Yageo America; Power_W: 50mW; TempCo: 350 ppm/C; Value_Code: 2R00; U/M: EA; Value: 2.00; EIA_Code: E96; Res_ohm: 2; SizeX_mm: 0.6; SizeY_mm: 0.3; SizeZ_mm: 0.26; Value2: 0.05W; SizeArea_mm2: 0.18; AEC Qualified: N; VDC_V: 25V; AEC Category: Q200
TP3U TP4U TP5U TP6U TP7U TP8U TP9U TP10U TP11U TP12U TP13U TP14U TP15U = CMP-0078143-3: TEST POINT.  No entry in BOM.
U4U U6U U7U U9U = CMP-0013422-3: UCD7xxx Low Side Power MOSFET Driver with Body Diode Conduction Sensing, DRS0006A (WSON-6); Manufacturer: Texas Instruments; SizeZ_mm: 0.8; SizeX_mm: 3; SizeArea_mm2: 9; CompType: IC; U/M: EA; SizeAreaWB_mm2: 16
U5U U8U = CMP-0097820-2: Manufacturer: Texas Instruments; AEC Category: Q200; CompType: IC; Standoff Height: 0mm; SizeZ_mm: 0.89mm

## Sheet PMP23340E3_UCD_Hardware.SchDoc
size 431 x 279 mm; Date: Not shown in title block; ApprovedBy: Not shown in title block; CheckedBy: Not shown in title block; Author: Not shown in title block; CompanyName: Not shown in title block; Engineer: Not shown in title block; Organization: Not shown in title block; Address1: Not shown in title block; Address2: Not shown in title block; Address3: Not shown in title block; Address4: Not shown in title block; DocumentNumber: 3; Revision: Use project parameter SCH_Rev; SheetNumber: 3; SheetTotal: 3; PageSetup: Record=PageOptions¦CenterHorizontal=True¦CenterVertical=True¦PrintScale=1.00¦XCorrection=1.00¦YCorrection=1.00¦PrintKind=0¦BorderSize=5000000¦LeftOffset=0¦BottomOffset=0¦Orientation=2¦PaperLength=1000¦PaperWidth=1000¦Scale=100¦PaperSource=15¦PrintQuality=600¦MediaType=1¦DitherType=10¦PaperKind=Letter¦PrintScaleMode=1
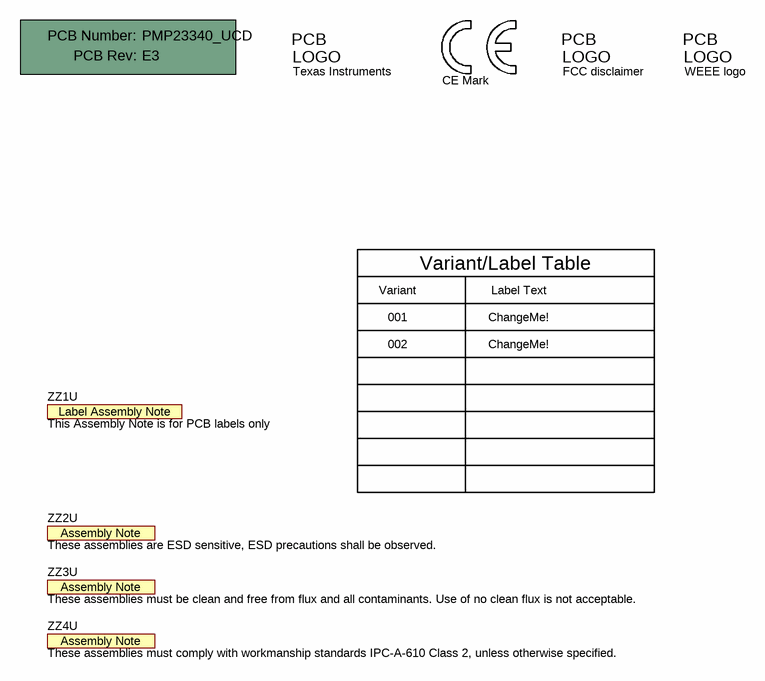
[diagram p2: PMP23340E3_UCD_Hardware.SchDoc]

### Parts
!PCB1U  Printed Circuit Board  (value not drawn)  (mechanical)
Logo1U  CE Mark  [CE_Mark_5mm]  (no BOM)
Logo2U  Texas Instruments  [TI_Symbol_Overlay_Small]  (no BOM)
Logo3U  FCC disclaimer  [FCC_disclaimer]  (no BOM)
Logo4U  WEEE logo  [WEEE_Minimum]  (no BOM)
ZZ1U  This Assembly Note is for PCB labels only  [AssemblyNoteLabel]  (no BOM)
ZZ2U  These assemblies are ESD sensitive, ESD precautions shall be observed.  [AssemblyNote]  (no BOM)
ZZ3U  These assemblies must be clean and free from flux and all contaminants. Use of no clean flux is not acceptable.  [AssemblyNote]  (no BOM)
ZZ4U  These assemblies must comply with workmanship standards IPC-A-610 Class 2, unless otherwise specified.  [AssemblyNote]  (no BOM)

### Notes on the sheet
- Variant
- Variant/Label Table
- Label Text
- 001
- 002
- ChangeMe!

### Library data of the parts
!PCB1U = CMP-0003618-2: Manufacturer: Any; PartNumber: PMP23340_UCD
Logo1U = CMP-0074844-1: SymbolCreator: a0412235
Logo2U = CMP-0074838-1: Texas Instrument Corporate Signature; SymbolCreator: a0412235; Lib Reference: TI_Logo; Library Reference: Logo
Logo3U = CMP-0074847-1: FCC_disclaimer; Library Reference: Logo
Logo4U = CMP-0074769-1
ZZ1U = CMP-0003616-3
ZZ2U = CMP-0077236-1
ZZ3U = CMP-0077237-1
ZZ4U = CMP-0077238-1

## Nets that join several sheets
AGND: PMP23340E3_UCD_Control (51 pins), PMP23340E3_UCD_Power_Stage (NT1U.2)
5V: PMP23340E3_UCD_Control (C24U.1 U3U.4 U3U.6), PMP23340E3_UCD_Power_Stage (9 pins)
DCT1A: PMP23340E3_UCD_Control (C12U.1 U1U.23), PMP23340E3_UCD_Power_Stage (R22U.1 R45U.1)
DCT1B: PMP23340E3_UCD_Control (C11U.1 U1U.22), PMP23340E3_UCD_Power_Stage (R31U.1 R36U.1)
PMBUS_SCL: PMP23340E3_UCD_Control (R3U.2 U1U.9), PMP23340E3_UCD_Power_Stage (J1U.6)
PMBUS_SDA: PMP23340E3_UCD_Control (R4U.2 U1U.10), PMP23340E3_UCD_Power_Stage (J1U.8)
PWM0A: PMP23340E3_UCD_Control (TP1U.1 U1U.11), PMP23340E3_UCD_Power_Stage (U5U.13)
PWM0B: PMP23340E3_UCD_Control (TP2U.1 U1U.12), PMP23340E3_UCD_Power_Stage (U5U.12)
PWM1A: PMP23340E3_UCD_Control (U1U.13), PMP23340E3_UCD_Power_Stage (R28U.1 R33U.1)
PWM1B: PMP23340E3_UCD_Control (U1U.14), PMP23340E3_UCD_Power_Stage (R19U.1 R42U.1)
PWM2A: PMP23340E3_UCD_Control (U1U.15), PMP23340E3_UCD_Power_Stage (U8U.12)
PWM2B: PMP23340E3_UCD_Control (U1U.16), PMP23340E3_UCD_Power_Stage (U8U.13)
Vin: PMP23340E3_UCD_Control (R8U.2), PMP23340E3_UCD_Power_Stage (21 pins)
Vout: PMP23340E3_UCD_Control (R6U.2 R7U.2), PMP23340E3_UCD_Power_Stage (184 pins)
Vsw1: PMP23340E3_UCD_Control (R13U.1), PMP23340E3_UCD_Power_Stage (19 pins)
Vsw2: PMP23340E3_UCD_Control (R11U.1), PMP23340E3_UCD_Power_Stage (18 pins)

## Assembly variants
001: not fitted C97 C98 C99 C110 C111 C112 C113 C114 R4 R8 R34 R36 R39 R44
